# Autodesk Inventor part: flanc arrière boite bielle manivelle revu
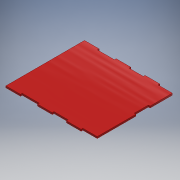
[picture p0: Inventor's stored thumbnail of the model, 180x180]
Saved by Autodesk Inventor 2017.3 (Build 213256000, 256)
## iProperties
Part Number: flanc arrière boite bielle manivelle revu
Material: Générique
Document SubType Name: Modeling
Designer: ficho
Density: 1 g/cm^3
Appearance: Rouge
Author: ficho
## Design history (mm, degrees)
sketch "Esquisse1"
  geometry: L1 (-25, 0)-(0, 0); L2 (30, 0)-(55, 0); L3 (80, 0)-(105, 0); L4 (0.15, 3)-(29.85, 3); L5 (55.15, 3)-(79.85, 3); L6 (105.15, 3)-(130, 3); L7 (-25, 0)-(-25, 133); L8 (130, 133)-(130, 3); L9 (0, 136)-(-25, 136); L10 (-25, 136)-(-25, 133); L11 (0.15, 133)-(29.85, 133); L12 (30, 136)-(55, 136); L13 (55.15, 133)-(79.85, 133); L14 (80, 136)-(105, 136); L15 (105.15, 133)-(130, 133); L16 (0, 136)-(0.15, 136); L17 (0.15, 136)-(0.15, 133); L18 (30, 136)-(29.85, 136); L19 (29.85, 136)-(29.85, 133); L20 (55, 136)-(55.15, 136); L21 (55.15, 136)-(55.15, 133); L22 (80, 136)-(79.85, 136); L23 (79.85, 136)-(79.85, 133); L24 (105, 136)-(105.15, 136); L25 (105.15, 136)-(105.15, 133); L26 (105, 0)-(105.15, 0); L27 (105.15, 0)-(105.15, 3); L28 (80, 0)-(79.85, 0); L29 (79.85, 0)-(79.85, 3); L30 (55, 0)-(55.15, 0); L31 (55.15, 0)-(55.15, 3); L32 (30, 0)-(29.85, 0); L33 (29.85, 0)-(29.85, 3); L34 (0, 0)-(0.15, 0); L35 (0.15, 0)-(0.15, 3)
  constraints: 70 end point, 1 point on line
extrude "Extrusion1" new body sketch "Esquisse1" distance "d2" = 3; taper "d3" = 0 deg
sketch "Esquisse2"
  geometry: L1 (130, 133)-(130, 3) reference; L2 (127, 94.616)-(127, 69.916); L3 (130, 69.916)-(130, 94.616); L4 (127, 94.616)-(130, 94.616); L5 (127, 69.916)-(130, 69.916); 1 further point
  constraints: 8 end point, 2 point on line, 1 parallel
extrude "Extrusion2" cut sketch "Esquisse2" distance "d6" = 3; taper "d7" = 0 deg
node "Solide1"
